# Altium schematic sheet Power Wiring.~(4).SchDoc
size B; Organization: Monterey Bay Aquarium Research Institute; Address1: 7700 Sandholdt Rd; Address2: Moss Landing, CA 95039-9644; CompanyName: MBARI
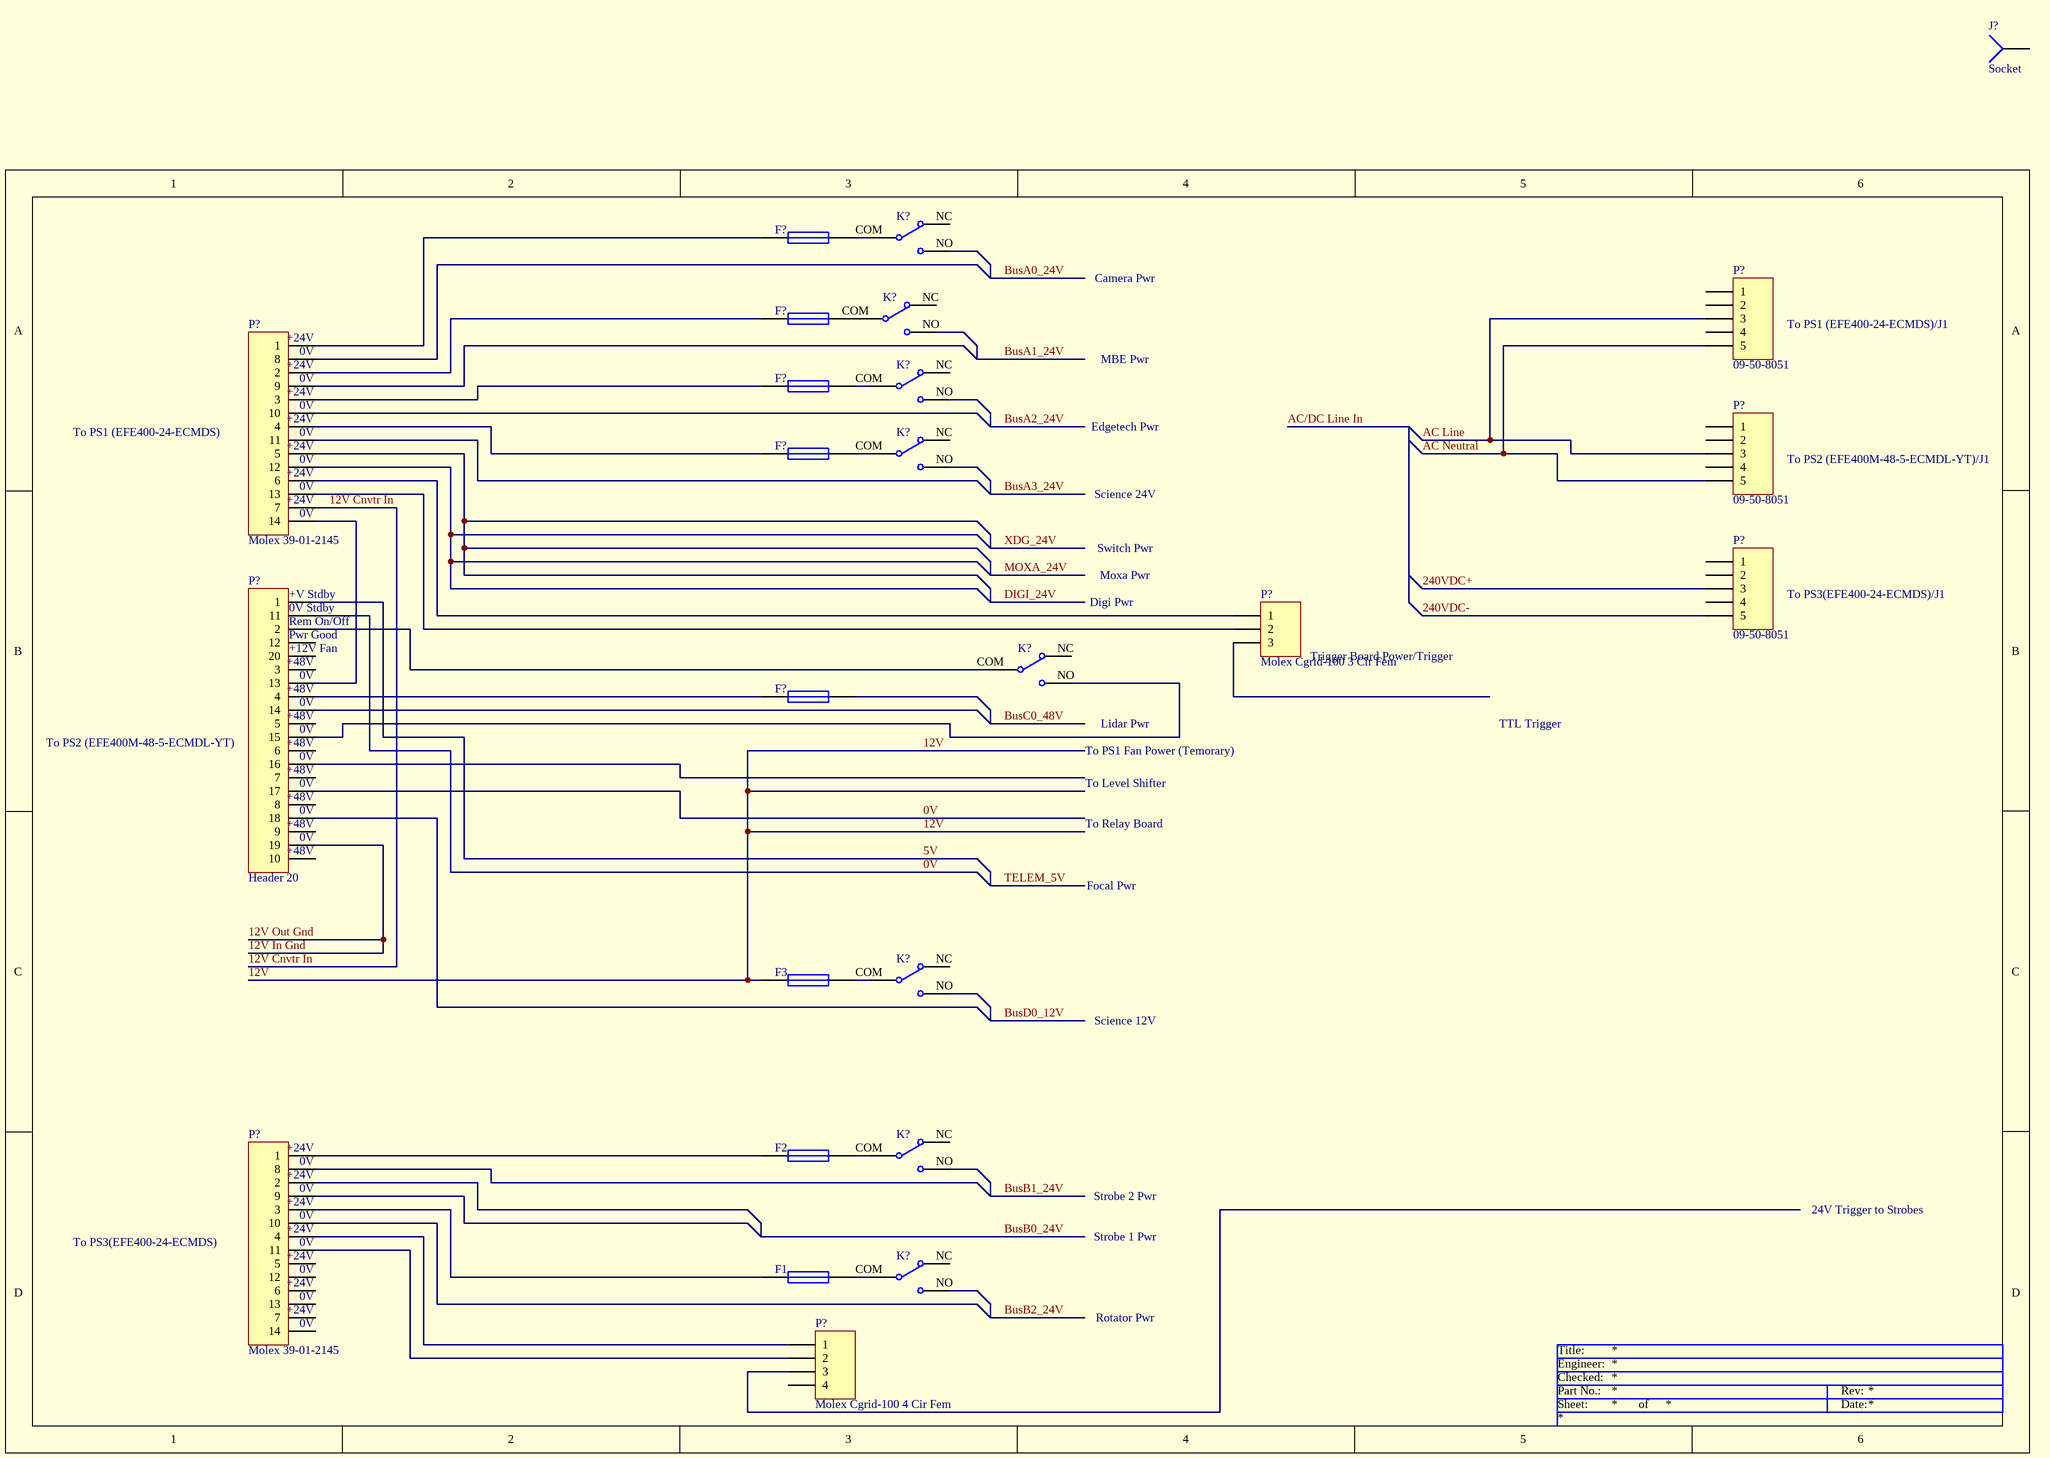
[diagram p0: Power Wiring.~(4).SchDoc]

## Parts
(Parts that share a designator on the sheet are numbered #1, #2 ... from top to bottom, then left to right.)
F1  Fuse 1  [PIN-W2/E2.8]  (value not drawn)
F2  Fuse 1  [PIN-W2/E2.8]  (value not drawn)
F3  Fuse 1  [PIN-W2/E2.8]  (value not drawn)
F?#1  Fuse 1  [PIN-W2/E2.8]  (value not drawn)
F?#2  Fuse 1  [PIN-W2/E2.8]  (value not drawn)
F?#3  Fuse 1  [PIN-W2/E2.8]  (value not drawn)
F?#4  Fuse 1  [PIN-W2/E2.8]  (value not drawn)
F?#5  Fuse 1  [PIN-W2/E2.8]  (value not drawn)
J?  Socket  [PIN1]
K?#1  SW-SPDT  [TL36WW15050]  (value not drawn)
K?#2  SW-SPDT  [TL36WW15050]  (value not drawn)
K?#3  SW-SPDT  [TL36WW15050]  (value not drawn)
K?#4  SW-SPDT  [TL36WW15050]  (value not drawn)
K?#5  SW-SPDT  [TL36WW15050]  (value not drawn)
K?#6  SW-SPDT  [TL36WW15050]  (value not drawn)
K?#7  SW-SPDT  [TL36WW15050]  (value not drawn)
K?#8  SW-SPDT  [TL36WW15050]  (value not drawn)
P?#1  09-50-8051  [HDR1X5]
P?#2  Molex 39-01-2145  [HDR1X14]
P?#3  09-50-8051  [HDR1X5]
P?#4  09-50-8051  [HDR1X5]
P?#5  Header 20  [HDR1X20]
P?#6  Molex Cgrid-100 3 Cir Fem  [HDR1X3]
P?#7  Molex 39-01-2145  [HDR1X14]
P?#8  Molex Cgrid-100 4 Cir Fem  [HDR1X4]

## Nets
0V: P?#5.11 P?#5.17
5V: P?#5.1
12V: F3.1
12V Cnvtr In: P?#2.7
12V In Gnd: P?#5.19  [also labelled 12V Out Gnd]
240VDC+: P?#4.3
240VDC-: P?#4.5
AC Line: P?#1.3 P?#3.3
AC Neutral: P?#1.5 P?#3.5
NetF1_1: F1.1 P?#7.3
NetF1_2: F1.2 K?#8.COM
NetF2_1: F2.1 P?#7.1
NetF2_2: F2.2 K?#7.COM
NetF3_2: F3.2 K?#6.COM
NetF?#1_1: F?#1.1 P?#2.1
NetF?#1_2: F?#1.2 K?#1.COM
NetF?#2_1: F?#2.1 P?#2.2
NetF?#2_2: F?#2.2 K?#2.COM
NetF?#3_1: F?#3.1 P?#2.3
NetF?#3_2: F?#3.2 K?#3.COM
NetF?#4_1: F?#4.1 P?#2.4
NetF?#4_2: F?#4.2 K?#4.COM
NetF?#5_1: F?#5.1 P?#5.4
NetK?#5_COM: K?#5.COM P?#5.2
NetK?#5_NO: K?#5.NO P?#5.15
NetP?#2_6: P?#2.6 P?#6.1
NetP?#2_13: P?#2.13 P?#6.2
NetP?#2_14: P?#2.14 P?#5.13
NetP?#7_4: P?#7.4 P?#8.1
NetP?#7_11: P?#7.11 P?#8.2

Not connected (* = marked no-connect by the designer): F?#5 2; J? 1; K?#1 NC(3) NO(1); K?#2 NC(3) NO(1); K?#3 NC(3) NO(1); K?#4 NC(3) NO(1); K?#5 NC(3); K?#6 NC(3) NO(1); K?#7 NC(3) NO(1); K?#8 NC(3) NO(1); P?#1 1 2 4; P?#2 5 8 9 10 11 12; P?#3 1 2 4; P?#4 1 2 4; P?#5 3 5 6 7 8 9 10 12 14 16 18 20; P?#6 3; P?#7 2 5 6 7 8 9 10 12 13 14; P?#8 3 4

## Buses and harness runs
bus AC/DC Line In
bus BusA0_24V
bus BusA1_24V
bus BusA2_24V
bus BusA3_24V
bus BusB0_24V
bus BusB1_24V
bus BusB2_24V
bus BusC0_48V
bus BusD0_12V
bus DIGI_24V
bus MOXA_24V
bus TELEM_5V
bus XDG_24V

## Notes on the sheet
- Camera Pwr
- To PS1 (EFE400-24-ECMDS)/J1
- (near P?#2) 0V
- (near P?#2) +24V
- MBE Pwr
- To PS1 (EFE400-24-ECMDS)
- Edgetech Pwr
- To PS2 (EFE400M-48-5-ECMDL-YT)/J1
- Science 24V
- (near P?#5) +V Stdby
- Digi Pwr
- Switch Pwr
- Moxa Pwr
- To PS3(EFE400-24-ECMDS)/J1
- (near P?#5) 0V Stdby
- (near P?#5) Rem On/Off
- (near P?#5) Pwr Good
- (near P?#5) +12V Fan
- (near P?#5) +48V
- (near P?#6) Trigger Board Power/Trigger
- (near P?#5) 0V
- Lidar Pwr
- TTL Trigger
- To PS2 (EFE400M-48-5-ECMDL-YT)
- To Level Shifter
- To PS1 Fan Power (Temorary)
- To Relay Board
- Focal Pwr
- Science 12V
- (near P?#7) 0V
- (near P?#7) +24V
- Strobe 2 Pwr
- 24V Trigger to Strobes
- To PS3(EFE400-24-ECMDS)
- Strobe 1 Pwr
- Rotator Pwr

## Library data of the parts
F1-F3 F?#1-F?#5 = Fuse 1: Fuse
K?#1-K?#8 = SW-SPDT: SPDT Subminiature Toggle Switch, Right Angle Mounting, Vertical Actuation
P?#1 P?#3 P?#4 = Header 5: Header, 5-Pin
P?#2 P?#7 = Header 14: Header, 14-Pin
P?#5 = Header 20: Header, 20-Pin
P?#6 = Header 3: Header, 3-Pin
P?#8 = Header 4: Header, 4-Pin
